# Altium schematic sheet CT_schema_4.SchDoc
size 250 x 258 mm
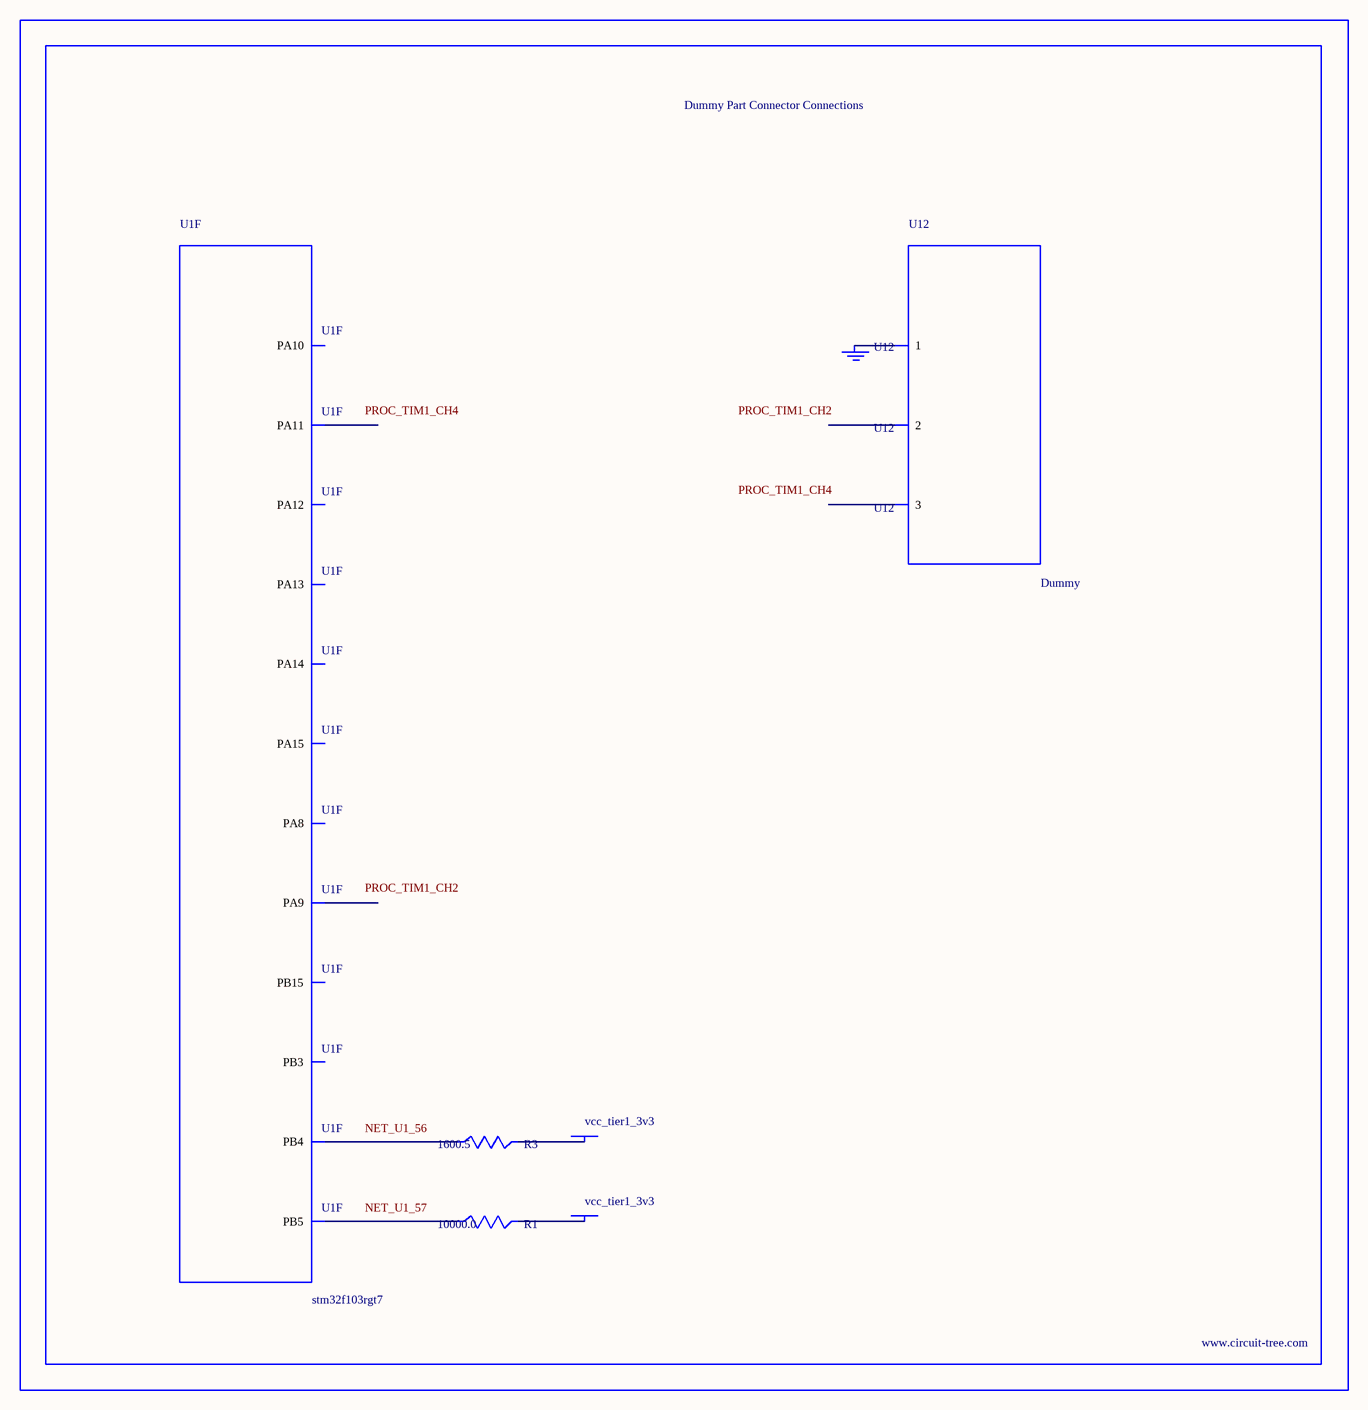
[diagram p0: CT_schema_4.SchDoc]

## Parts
BORDER3  (no value)
GND_INSTANCE_3_0  (no value)
POWER_INSTANCE_3_0  vcc_tier1_3v3
POWER_INSTANCE_3_1  vcc_tier1_3v3
R1  10000.0  [R0603]
R3  1600.5  [R0603]
U1  stm32f103rgt7  [LQFP64]  (part F of 6)
U12  Dummy  [DUMMY_PACKAGE_153]

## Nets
NetGND_INSTANCE_3_0_0: GND_INSTANCE_3_0.0(GND) U12.1
NetPOWER_INSTANCE_3_0_0: POWER_INSTANCE_3_0.0(PWR) R3.2
NetPOWER_INSTANCE_3_1_0: POWER_INSTANCE_3_1.0(PWR) R1.2
NetR1_1: R1.1 U1.57(PB5)
NetR3_1: R3.1 U1.56(PB4)

Not connected (* = marked no-connect by the designer): U1 36(PB15) 41(PA8) 42(PA9) 43(PA10) 44(PA11) 45(PA12) 46(PA13) 49(PA14) 50(PA15) 55(PB3); U12 2 3

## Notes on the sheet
- Labels drawn without touching a wire or pin: NET_U1_56, NET_U1_57, PROC_TIM1_CH2, PROC_TIM1_CH4

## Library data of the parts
BORDER3 = BORDER_PAGE3
GND_INSTANCE_3_0 = GND
POWER_INSTANCE_3_0 POWER_INSTANCE_3_1 = PWR
R1 = RC0603JR-0710KL
R3 = R3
